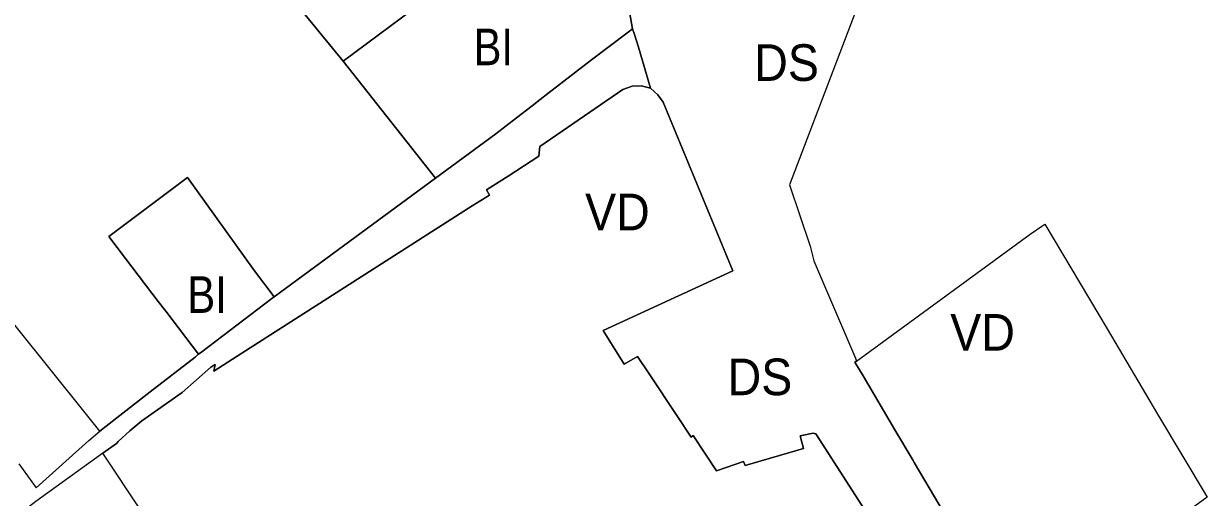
# Model space of a CAD drawing. Extents: x -650451 to -642268, y -1075216 to -1066610.
# Drawn here: x -647477.1 to -647089.5, y -1072156.5 to -1072001.3 of the extents above; entities that cross this region are included whole.
import ezdxf

# ---------------------------------------------------------------- set-up
doc = ezdxf.new("R2010")
doc.units = 0
doc.header["$LTSCALE"] = 4.8
for name, color, linetype, lineweight in [('15', 7, 'Continuous', 13), ('18', 7, 'Continuous', 13), ('2', 7, 'Continuous', 13), ('24', 7, 'Continuous', 13), ('35', 7, 'Continuous', 13)]:
    doc.layers.add(name, color=color, linetype=linetype, lineweight=lineweight)
doc.layers.add('62', color=7, linetype='Continuous')

msp = doc.modelspace()

# ---------------------------------------------------------------- linework, layer by layer
at = {"layer": '15'}
for points in [[(-647342.24, -1072051.96), (-647322.51, -1072037.39), (-647315.71, -1072032.16), (-647310.59, -1072028.2), (-647308.02, -1072026.22), (-647305.46, -1072024.24), (-647291.19, -1072013.22), (-647279.22, -1072004.14), (-647277.74, -1072003.02)], [(-647277.74, -1072003.02), (-647277.14, -1072004.87), (-647275.78, -1072009.02), (-647271.92, -1072022.5)], [(-647271.92, -1072022.5), (-647274.99, -1072021.69), (-647277.91, -1072021.81), (-647280.99, -1072022.86), (-647308.09, -1072041.53), (-647308.4, -1072044.8), (-647318.52, -1072051.32), (-647325.64, -1072055.78), (-647324.59, -1072057.48), (-647330.25, -1072061.07), (-647405.76, -1072109.33), (-647414.89, -1072115.23), (-647414.48, -1072113.03), (-647415.85, -1072113.9), (-647425.23, -1072122.14), (-647438.51, -1072131.51), (-647442.42, -1072134.72), (-647446.17, -1072138.29), (-647446.78, -1072138.88), (-647451.21, -1072142.08)], [(-647419.85, -1072109.65), (-647418.82, -1072108.85), (-647395.88, -1072091.34), (-647395.13, -1072090.79), (-647342.24, -1072051.96)], [(-647452.23, -1072134.91), (-647450.18, -1072133.18), (-647435.69, -1072121.94), (-647421.04, -1072110.57), (-647419.85, -1072109.65)], [(-647478.73, -1072145.53), (-647473.022, -1072153.375), (-647455.83, -1072137.96), (-647452.23, -1072134.91)], [(-647451.21, -1072142.08), (-647473.12, -1072157.91), (-647475.57, -1072159.74), (-647447.73, -1072195.72), (-647407.34, -1072247.93), (-647404.45, -1072250.66), (-647396.25, -1072252.14), (-647392.34, -1072250.02), (-647376.68, -1072222.29)]]:
    msp.add_lwpolyline(points, dxfattribs=at)
at = {"layer": '18'}
for points in [[(-647287.04, -1071950.34), (-647342.705, -1071991.503), (-647345.75, -1071993.72), (-647372.56, -1072013.58)], [(-647372.56, -1072013.58), (-647393.87, -1071987.45), (-647406.14, -1071989.31), (-647408.85, -1071951.95)]]:
    msp.add_lwpolyline(points, dxfattribs=at)
at = {"layer": '2'}
for points in [[(-647372.56, -1072013.58), (-647345.75, -1071993.72), (-647342.705, -1071991.503), (-647287.04, -1071950.34), (-647277.74, -1072003.02)], [(-647277.74, -1072003.02), (-647279.22, -1072004.14), (-647291.19, -1072013.22), (-647305.46, -1072024.24), (-647308.02, -1072026.22), (-647310.59, -1072028.2), (-647315.71, -1072032.16), (-647322.51, -1072037.39), (-647342.24, -1072051.96), (-647372.56, -1072013.58)], [(-647419.85, -1072109.65), (-647430.62, -1072095.59), (-647433.06, -1072092.41), (-647443.85, -1072078.33), (-647449.29, -1072071.08), (-647423.49, -1072051.76), (-647401.58, -1072082.32), (-647395.13, -1072090.79)], [(-647395.13, -1072090.79), (-647395.88, -1072091.34), (-647418.82, -1072108.85), (-647419.85, -1072109.65)]]:
    msp.add_lwpolyline(points, dxfattribs=at)
at = {"layer": '24'}
for points in [[(-647271.92, -1072022.5), (-647275.78, -1072009.02), (-647277.14, -1072004.87), (-647277.74, -1072003.02), (-647287.04, -1071950.34)], [(-647261.12, -1071954.82), (-647259.7, -1071957.06), (-647256.53, -1071968.64), (-647253.85, -1071964.38), (-647249.92, -1071958.12), (-647201.53, -1071988.71), (-647226.41, -1072054.11), (-647219.64, -1072074.29), (-647218.42, -1072079.01), (-647216.23, -1072084.14), (-647204.78, -1072110.92), (-647204.38, -1072111.87)], [(-647172.69, -1072205.9), (-647191.99, -1072175.85), (-647217.78, -1072135.69), (-647218.57, -1072135.49), (-647222.92, -1072136.43), (-647221.74, -1072140.53), (-647240.91, -1072146.14), (-647241.44, -1072144.76), (-647250.31, -1072147.84), (-647257.88, -1072136.31), (-647258.54, -1072136.82), (-647263.07, -1072130.02), (-647272.55, -1072115.78), (-647276.11, -1072110.44), (-647280.56, -1072112.9), (-647287.34, -1072101.88), (-647244.88, -1072082.33), (-647267.71, -1072027.09), (-647269.43, -1072024.67), (-647271.92, -1072022.5)], [(-647204.38, -1072111.87), (-647204.93, -1072112.27), (-647202.29, -1072116.75), (-647191.84, -1072134.47), (-647185.91, -1072144.49), (-647185.52, -1072145.16), (-647177.46, -1072158.82), (-647168.75, -1072172.78), (-647152.87, -1072198.24), (-647151.05, -1072201.21)]]:
    msp.add_lwpolyline(points, dxfattribs=at)
at = {"layer": '35'}
for points in [[(-647408.85, -1071951.95), (-647406.14, -1071989.31), (-647393.87, -1071987.45), (-647372.56, -1072013.58), (-647342.24, -1072051.96), (-647395.13, -1072090.79)], [(-647452.23, -1072134.91), (-647472.86, -1072109.13), (-647474.72, -1072106.81), (-647485.6, -1072093.2), (-647504.73, -1072069.29), (-647542.57, -1072021.99)], [(-647451.21, -1072142.08), (-647446.78, -1072138.88), (-647446.17, -1072138.29), (-647442.42, -1072134.72), (-647438.51, -1072131.51), (-647425.23, -1072122.14), (-647415.85, -1072113.9), (-647414.48, -1072113.03), (-647414.89, -1072115.23), (-647405.76, -1072109.33), (-647330.25, -1072061.07), (-647324.59, -1072057.48), (-647325.64, -1072055.78), (-647318.52, -1072051.32), (-647308.4, -1072044.8), (-647308.09, -1072041.53), (-647280.99, -1072022.86), (-647277.91, -1072021.81), (-647274.99, -1072021.69), (-647271.92, -1072022.5)], [(-647271.92, -1072022.5), (-647269.43, -1072024.67), (-647267.71, -1072027.09), (-647244.88, -1072082.33), (-647287.34, -1072101.88), (-647280.56, -1072112.9), (-647276.11, -1072110.44), (-647272.55, -1072115.78), (-647263.07, -1072130.02), (-647258.54, -1072136.82), (-647257.88, -1072136.31), (-647250.31, -1072147.84), (-647241.44, -1072144.76), (-647240.91, -1072146.14), (-647221.74, -1072140.53), (-647222.92, -1072136.43), (-647218.57, -1072135.49), (-647217.78, -1072135.69), (-647191.99, -1072175.85), (-647172.69, -1072205.9)], [(-647395.13, -1072090.79), (-647401.58, -1072082.32), (-647423.49, -1072051.76), (-647449.29, -1072071.08), (-647443.85, -1072078.33), (-647433.06, -1072092.41), (-647430.62, -1072095.59), (-647419.85, -1072109.65)], [(-647204.38, -1072111.87), (-647147.54, -1072070.29), (-647143.76, -1072067.69), (-647142.77, -1072067), (-647122.33, -1072101.34), (-647105.82, -1072129.3), (-647089.54, -1072156.53), (-647134.17, -1072188.95), (-647151.05, -1072201.21)], [(-647419.85, -1072109.65), (-647421.04, -1072110.57), (-647435.69, -1072121.94), (-647450.18, -1072133.18), (-647452.23, -1072134.91)], [(-647151.05, -1072201.21), (-647152.87, -1072198.24), (-647168.75, -1072172.78), (-647177.46, -1072158.82), (-647185.52, -1072145.16), (-647185.91, -1072144.49), (-647191.84, -1072134.47), (-647202.29, -1072116.75), (-647204.93, -1072112.27), (-647204.38, -1072111.87)], [(-647376.68, -1072222.29), (-647401.221, -1072217.342), (-647451.21, -1072142.08)]]:
    msp.add_lwpolyline(points, dxfattribs=at)

# ---------------------------------------------------------------- texts
at = {"layer": '62'}
for s, width, p in [('BI', 0.85, (-647329.802, -1072014.949)), ('DS', 0.95, (-647237.915, -1072020.083)), ('VD', 0.95, (-647293.302, -1072069.038)), ('BI', 0.85, (-647423.542, -1072096.109)), ('VD', 0.95, (-647173.72, -1072108.474)), ('DS', 0.95, (-647246.634, -1072123.069))]:
    msp.add_text(s, height=12, dxfattribs=dict(at, width=width)).set_placement(p)

doc.saveas('drawing.dxf')
